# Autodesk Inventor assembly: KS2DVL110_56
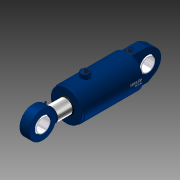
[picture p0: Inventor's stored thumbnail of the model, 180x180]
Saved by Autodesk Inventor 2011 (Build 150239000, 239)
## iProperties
Created: 2010-10
Document SubType Name: Assembly
Designer: TB
Mass: 566.294 g
Surface Area: 1153.75 cm^2
Volume: 566.294 cm^3
Density: 1 g/cm^3
Description: KS2DVL 110/56 - 100 mm
Slaglengde: 100,000 mm
Author: TB
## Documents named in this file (6)
- C:\Vault\Sylinderteknikk\Projects_ST\3D.nettkatalog\KS2-Series\KS2DVL\KS2DVL110_56\KS2DVL110_56.iam
- C:\Vault\Sylinderteknikk\Projects_ST\3D.nettkatalog\KS2-Series\KS2DVL\KS2DVL110_56\KS2DVL110_56_stang.ipt
- C:\Vault\Sylinderteknikk\Projects_ST\3D.nettkatalog\KS2-Series\KS2DVL\KS2DVL110_56\KS2DVL110_56_Parameters.ipt
- C:\Vault\Sylinderteknikk\Projects_ST\3D.nettkatalog\KS2-Series\KS2DVL\KS2DVL110_56\KS2DVL110_56_body..ipt
- C:\Vault\Sylinderteknikk\Projects_ST\Øyer\Klinkby.KS.Øyer\KS.50.eye.Komplett\KS.50.eye.komplett.ipt
- C:\Vault\Sylinderteknikk\Projects_ST\Øyer\Klinkby.KS.Øyer\KS.50.eye.Komplett\Kule50HO.ipt
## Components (5 placed, 5 different names)
1. KS2DVL110_56_Parameters:3
2. KS2DVL110_56_stang:1 — Mate:1, FriMate:2, Mate:3, Insert:1
3. KS2DVL110_56_body.:1 — Mate:1, FriMate:2, Mate:3, Angle:1, Insert:2
4. KS.50.eye.komplett:1 — Insert:1, Angle:1
5. Kule50HO:1 — Insert:2
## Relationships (6: Mate 3, Insert 2, Angle 1)
- Mate:1: KS2DVL110_56_stang:1 ↔ KS2DVL110_56_body.:1
- FriMate:2 [Mate]: KS2DVL110_56_stang:1 ↔ KS2DVL110_56_body.:1
- Mate:3: KS2DVL110_56_stang:1 ↔ KS2DVL110_56_body.:1
- Insert:1: KS2DVL110_56_stang:1 ↔ KS.50.eye.komplett:1
- Angle:1: KS2DVL110_56_body.:1 ↔ KS.50.eye.komplett:1
- Insert:2: KS2DVL110_56_body.:1 ↔ Kule50HO:1
## Named parameters: Forlengelse_rør = 0, Vinkel_Minusport = 0
